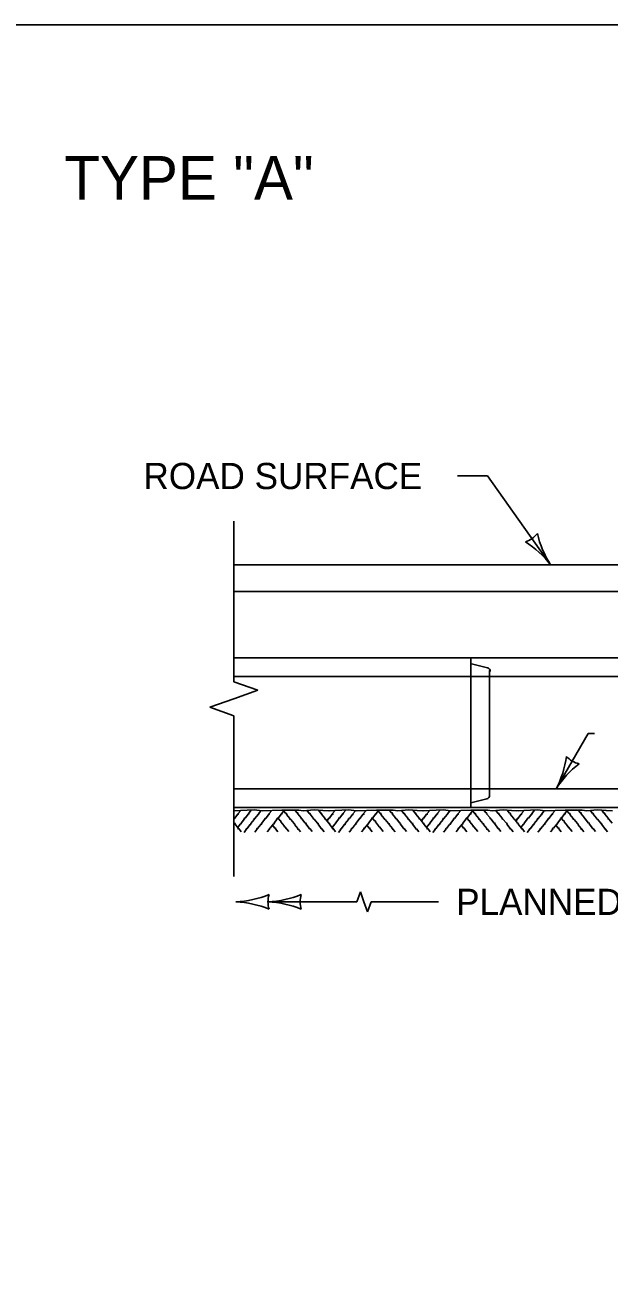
# Model space of a CAD drawing. Extents: x 49991.4 to 50022.1, y 49985 to 50011.4.
# Drawn here: x 50003.224 to 50004.56, y 49996.145 to 49998.999 of the extents above; entities that cross this region are included whole.
import ezdxf

# ---------------------------------------------------------------- set-up
doc = ezdxf.new("R2010")
doc.units = 0
for name, color, linetype in [('Level 1', 7, 'Continuous'), ('Level 2', 7, 'Continuous'), ('Level 3', 7, 'Continuous'), ('Level 4', 7, 'Continuous'), ('Level 6', 7, 'Continuous')]:
    doc.layers.add(name, color=color, linetype=linetype)

msp = doc.modelspace()

# ---------------------------------------------------------------- linework, layer by layer
at = {"layer": 'Level 1'}
for p, q in [((50003.7019, 49997.7029), (50003.702, 49997.7636)), ((50003.702, 49997.7636), (50004.9281, 49997.7636)), ((50005.2161, 49997.7029), (50003.7019, 49997.7029)), ((50003.7036, 49997.7029), (50003.7047, 49997.7029)), ((50003.702, 49997.5504), (50005.9421, 49997.5504)), ((50004.2441, 49997.5504), (50004.2441, 49997.208)), ((50006.3273, 49997.208), (50003.702, 49997.208))]:
    msp.add_line(p, q, dxfattribs=at)
msp.add_lwpolyline([(49999.3835, 49998.9992), (50016.7501, 49998.9992), (50016.7501, 49987.7988), (49999.3835, 49987.7988)], close=True, dxfattribs=at)
for points in [[(50003.7015, 49997.2006), (50003.7485, 49997.2025), (50003.7665, 49997.2004), (50003.8121, 49997.2019), (50003.8505, 49997.2022), (50003.8609, 49997.2007), (50003.8861, 49997.2025), (50003.9055, 49997.2013), (50003.9201, 49997.2006)], [(50003.7179, 49997.2012), (50003.7119, 49997.1941), (50003.7125, 49997.1926), (50003.7109, 49997.1926), (50003.7037, 49997.183), (50003.7029, 49997.183)], [(50003.742, 49997.202), (50003.736, 49997.195), (50003.7367, 49997.1936), (50003.7353, 49997.1936), (50003.7279, 49997.184), (50003.7258, 49997.184), (50003.7263, 49997.1824), (50003.7185, 49997.1726), (50003.7185, 49997.171), (50003.7168, 49997.1704), (50003.7108, 49997.1626)], [(50003.7639, 49997.2004), (50003.7585, 49997.1936), (50003.7589, 49997.1923), (50003.7577, 49997.1923), (50003.7503, 49997.1827), (50003.7483, 49997.1827), (50003.7485, 49997.181), (50003.7408, 49997.1713), (50003.7408, 49997.1696), (50003.7391, 49997.1689), (50003.7319, 49997.1596), (50003.7301, 49997.1593), (50003.7305, 49997.1576), (50003.7253, 49997.151)], [(50003.7888, 49997.2012), (50003.7828, 49997.1941), (50003.7835, 49997.1926), (50003.7821, 49997.1926), (50003.7749, 49997.183), (50003.7727, 49997.183), (50003.7729, 49997.1812), (50003.7654, 49997.1718), (50003.7654, 49997.1698), (50003.7635, 49997.1692), (50003.7564, 49997.1598), (50003.7545, 49997.1598), (50003.7549, 49997.1578), (50003.7497, 49997.1515)], [(50003.8173, 49997.202), (50003.8115, 49997.1947), (50003.8121, 49997.1935), (50003.8109, 49997.1935), (50003.8033, 49997.1839), (50003.8014, 49997.1839), (50003.8015, 49997.1822), (50003.7939, 49997.1726), (50003.7939, 49997.1707), (50003.7923, 49997.1702), (50003.7849, 49997.1608), (50003.7833, 49997.1606), (50003.7835, 49997.1587), (50003.7783, 49997.1524)], [(50003.8547, 49997.1524), (50003.8499, 49997.1587), (50003.8483, 49997.1584), (50003.8487, 49997.1598), (50003.841, 49997.169), (50003.8415, 49997.171), (50003.8397, 49997.1712), (50003.832, 49997.1808), (50003.8303, 49997.1812), (50003.8301, 49997.183), (50003.8225, 49997.1922), (50003.8229, 49997.1941), (50003.8211, 49997.1941), (50003.8158, 49997.2006)], [(50003.8811, 49997.153), (50003.8755, 49997.1602), (50003.874, 49997.1599), (50003.8743, 49997.1612), (50003.8667, 49997.1706), (50003.8673, 49997.1725), (50003.8653, 49997.1726), (50003.8577, 49997.1824), (50003.856, 49997.1827), (50003.8559, 49997.1845), (50003.8483, 49997.1936), (50003.8485, 49997.1956), (50003.8465, 49997.1956), (50003.8415, 49997.202)], [(50003.9089, 49997.1522), (50003.9034, 49997.1596), (50003.9019, 49997.1592), (50003.9021, 49997.1605), (50003.8949, 49997.1701), (50003.8951, 49997.1718), (50003.8933, 49997.172), (50003.8855, 49997.1816), (50003.8839, 49997.1821), (50003.8837, 49997.1838), (50003.8763, 49997.193), (50003.8764, 49997.1947), (50003.8745, 49997.1947), (50003.8695, 49997.2016)], [(50003.919, 49997.1726), (50003.9118, 49997.1816), (50003.9101, 49997.1822), (50003.91, 49997.1839), (50003.9023, 49997.193), (50003.9027, 49997.195), (50003.9009, 49997.195), (50003.8953, 49997.2019)], [(50003.9175, 49997.2006), (50003.9645, 49997.2025), (50003.9823, 49997.2004), (50004.0281, 49997.2019), (50004.0665, 49997.2022), (50004.0773, 49997.2007), (50004.1021, 49997.2025), (50004.1213, 49997.2013), (50004.1361, 49997.2006)], [(50003.9339, 49997.2012), (50003.9279, 49997.1941), (50003.9285, 49997.1926), (50003.9269, 49997.1926), (50003.9197, 49997.183), (50003.9189, 49997.183)], [(50003.958, 49997.202), (50003.952, 49997.195), (50003.9527, 49997.1936), (50003.9513, 49997.1936), (50003.9439, 49997.184), (50003.9418, 49997.184), (50003.9423, 49997.1824), (50003.9345, 49997.1726), (50003.9345, 49997.171), (50003.9328, 49997.1704), (50003.9267, 49997.1626)], [(50003.9799, 49997.2004), (50003.9743, 49997.1936), (50003.9749, 49997.1923), (50003.9735, 49997.1923), (50003.9663, 49997.1827), (50003.9643, 49997.1827), (50003.9645, 49997.181), (50003.9568, 49997.1713), (50003.9568, 49997.1696), (50003.9551, 49997.1689), (50003.9478, 49997.1596), (50003.9461, 49997.1593), (50003.9465, 49997.1576), (50003.9411, 49997.151)], [(50004.0048, 49997.2012), (50003.9987, 49997.1941), (50003.9994, 49997.1926), (50003.9981, 49997.1926), (50003.9905, 49997.183), (50003.9887, 49997.183), (50003.9889, 49997.1812), (50003.9813, 49997.1718), (50003.9813, 49997.1698), (50003.9795, 49997.1692), (50003.9723, 49997.1598), (50003.9705, 49997.1598), (50003.9709, 49997.1578), (50003.9657, 49997.1515)], [(50004.0333, 49997.202), (50004.0273, 49997.1947), (50004.0281, 49997.1935), (50004.0265, 49997.1935), (50004.0193, 49997.1839), (50004.0174, 49997.1839), (50004.0175, 49997.1822), (50004.0099, 49997.1726), (50004.0099, 49997.1707), (50004.0083, 49997.1702), (50004.0009, 49997.1608), (50003.9993, 49997.1606), (50003.9995, 49997.1587), (50003.9941, 49997.1524)], [(50004.0707, 49997.1524), (50004.0659, 49997.1587), (50004.0643, 49997.1584), (50004.0645, 49997.1598), (50004.057, 49997.169), (50004.0573, 49997.171), (50004.0557, 49997.1712), (50004.048, 49997.1808), (50004.0463, 49997.1812), (50004.0461, 49997.183), (50004.0385, 49997.1922), (50004.0389, 49997.1941), (50004.0369, 49997.1941), (50004.0318, 49997.2006)], [(50004.0971, 49997.153), (50004.0915, 49997.1602), (50004.09, 49997.1599), (50004.0901, 49997.1612), (50004.0827, 49997.1706), (50004.0829, 49997.1725), (50004.0813, 49997.1726), (50004.0737, 49997.1824), (50004.072, 49997.1827), (50004.0719, 49997.1845), (50004.0643, 49997.1936), (50004.0645, 49997.1956), (50004.0625, 49997.1956), (50004.0575, 49997.202)], [(50004.1249, 49997.1522), (50004.1194, 49997.1596), (50004.1179, 49997.1592), (50004.1181, 49997.1605), (50004.1105, 49997.1701), (50004.111, 49997.1718), (50004.1093, 49997.172), (50004.1015, 49997.1816), (50004.0999, 49997.1821), (50004.0997, 49997.1838), (50004.0923, 49997.193), (50004.0924, 49997.1947), (50004.0905, 49997.1947), (50004.0855, 49997.2016)], [(50004.135, 49997.1726), (50004.1278, 49997.1816), (50004.126, 49997.1822), (50004.1259, 49997.1839), (50004.1183, 49997.193), (50004.1185, 49997.195), (50004.1165, 49997.195), (50004.1113, 49997.2019)], [(50004.1335, 49997.2006), (50004.1805, 49997.2025), (50004.1983, 49997.2004), (50004.2441, 49997.2019), (50004.2825, 49997.2022), (50004.2929, 49997.2007), (50004.318, 49997.2025), (50004.3373, 49997.2013), (50004.3521, 49997.2006)], [(50004.1499, 49997.2012), (50004.1439, 49997.1941), (50004.1445, 49997.1926), (50004.1429, 49997.1926), (50004.1357, 49997.183), (50004.1349, 49997.183)], [(50004.1739, 49997.202), (50004.168, 49997.195), (50004.1685, 49997.1936), (50004.1673, 49997.1936), (50004.1597, 49997.184), (50004.1578, 49997.184), (50004.1579, 49997.1824), (50004.1503, 49997.1726), (50004.1503, 49997.171), (50004.1487, 49997.1704), (50004.1427, 49997.1626)], [(50004.1959, 49997.2004), (50004.1905, 49997.1936), (50004.1909, 49997.1923), (50004.1897, 49997.1923), (50004.1823, 49997.1827), (50004.1803, 49997.1827), (50004.1805, 49997.181), (50004.1728, 49997.1713), (50004.1728, 49997.1696), (50004.1711, 49997.1689), (50004.1638, 49997.1596), (50004.162, 49997.1593), (50004.1623, 49997.1576), (50004.1571, 49997.151)], [(50004.2208, 49997.2012), (50004.2147, 49997.1941), (50004.2154, 49997.1926), (50004.2141, 49997.1926), (50004.2065, 49997.183), (50004.2047, 49997.183), (50004.2049, 49997.1812), (50004.1973, 49997.1718), (50004.1973, 49997.1698), (50004.1955, 49997.1692), (50004.1883, 49997.1598), (50004.1865, 49997.1598), (50004.1867, 49997.1578), (50004.1815, 49997.1515)], [(50004.2493, 49997.202), (50004.2433, 49997.1947), (50004.2441, 49997.1935), (50004.2425, 49997.1935), (50004.2353, 49997.1839), (50004.2334, 49997.1839), (50004.2335, 49997.1822), (50004.2259, 49997.1726), (50004.2259, 49997.1707), (50004.2243, 49997.1702), (50004.2169, 49997.1608), (50004.2149, 49997.1606), (50004.2154, 49997.1587), (50004.2101, 49997.1524)], [(50004.2867, 49997.1524), (50004.2819, 49997.1587), (50004.2803, 49997.1584), (50004.2805, 49997.1598), (50004.273, 49997.169), (50004.2733, 49997.171), (50004.2717, 49997.1712), (50004.264, 49997.1808), (50004.2623, 49997.1812), (50004.2621, 49997.183), (50004.2544, 49997.1922), (50004.2549, 49997.1941), (50004.2529, 49997.1941), (50004.2478, 49997.2006)], [(50004.3129, 49997.153), (50004.3075, 49997.1602), (50004.306, 49997.1599), (50004.3061, 49997.1612), (50004.2987, 49997.1706), (50004.2989, 49997.1725), (50004.2973, 49997.1726), (50004.2897, 49997.1824), (50004.288, 49997.1827), (50004.2879, 49997.1845), (50004.2801, 49997.1936), (50004.2805, 49997.1956), (50004.2785, 49997.1956), (50004.2735, 49997.202)], [(50004.3408, 49997.1522), (50004.3354, 49997.1596), (50004.3337, 49997.1592), (50004.3341, 49997.1605), (50004.3265, 49997.1701), (50004.327, 49997.1718), (50004.3253, 49997.172), (50004.3175, 49997.1816), (50004.3159, 49997.1821), (50004.3157, 49997.1838), (50004.3079, 49997.193), (50004.3084, 49997.1947), (50004.3065, 49997.1947), (50004.3015, 49997.2016)], [(50004.3509, 49997.1726), (50004.3437, 49997.1816), (50004.342, 49997.1822), (50004.3419, 49997.1839), (50004.3343, 49997.193), (50004.3345, 49997.195), (50004.3325, 49997.195), (50004.3273, 49997.2019)], [(50004.3495, 49997.2006), (50004.3965, 49997.2025), (50004.4143, 49997.2004), (50004.4599, 49997.2019), (50004.4983, 49997.2022), (50004.5089, 49997.2007), (50004.534, 49997.2025), (50004.5533, 49997.2013), (50004.5679, 49997.2006)], [(50004.3659, 49997.2012), (50004.3599, 49997.1941), (50004.3605, 49997.1926), (50004.3589, 49997.1926), (50004.3515, 49997.183), (50004.3505, 49997.183)], [(50004.3899, 49997.202), (50004.3839, 49997.195), (50004.3845, 49997.1936), (50004.3833, 49997.1936), (50004.3757, 49997.184), (50004.3738, 49997.184), (50004.3739, 49997.1824), (50004.3663, 49997.1726), (50004.3663, 49997.171), (50004.3647, 49997.1704), (50004.3587, 49997.1626)], [(50004.4119, 49997.2004), (50004.4063, 49997.1936), (50004.4069, 49997.1923), (50004.4055, 49997.1923), (50004.3983, 49997.1827), (50004.3963, 49997.1827), (50004.3965, 49997.181), (50004.3888, 49997.1713), (50004.3888, 49997.1696), (50004.3871, 49997.1689), (50004.3798, 49997.1596), (50004.378, 49997.1593), (50004.3783, 49997.1576), (50004.3731, 49997.151)], [(50004.4367, 49997.2012), (50004.4307, 49997.1941), (50004.4314, 49997.1926), (50004.4299, 49997.1926), (50004.4225, 49997.183), (50004.4207, 49997.183), (50004.4209, 49997.1812), (50004.4133, 49997.1718), (50004.4133, 49997.1698), (50004.4115, 49997.1692), (50004.4043, 49997.1598), (50004.4023, 49997.1598), (50004.4027, 49997.1578), (50004.3975, 49997.1515)], [(50004.4651, 49997.202), (50004.4593, 49997.1947), (50004.4601, 49997.1935), (50004.4585, 49997.1935), (50004.4513, 49997.1839), (50004.4493, 49997.1839), (50004.4495, 49997.1822), (50004.4419, 49997.1726), (50004.4419, 49997.1707), (50004.4403, 49997.1702), (50004.4329, 49997.1608), (50004.4309, 49997.1606), (50004.4314, 49997.1587), (50004.4261, 49997.1524)], [(50004.5027, 49997.1524), (50004.4979, 49997.1587), (50004.4961, 49997.1584), (50004.4965, 49997.1598), (50004.489, 49997.169), (50004.4893, 49997.171), (50004.4877, 49997.1712), (50004.48, 49997.1808), (50004.4783, 49997.1812), (50004.4781, 49997.183), (50004.4704, 49997.1922), (50004.4709, 49997.1941), (50004.4689, 49997.1941), (50004.4638, 49997.2006)], [(50004.5291, 49997.153), (50004.5235, 49997.1602), (50004.5219, 49997.1599), (50004.5221, 49997.1612), (50004.5147, 49997.1706), (50004.5149, 49997.1725), (50004.5133, 49997.1726), (50004.5057, 49997.1824), (50004.504, 49997.1827), (50004.5039, 49997.1845), (50004.4961, 49997.1936), (50004.4965, 49997.1956), (50004.4945, 49997.1956), (50004.4895, 49997.202)], [(50004.5568, 49997.1522), (50004.5514, 49997.1596), (50004.5497, 49997.1592), (50004.5501, 49997.1605), (50004.5425, 49997.1701), (50004.543, 49997.1718), (50004.5411, 49997.172), (50004.5335, 49997.1816), (50004.5319, 49997.1821), (50004.5315, 49997.1838), (50004.5239, 49997.193), (50004.5244, 49997.1947), (50004.5225, 49997.1947), (50004.5175, 49997.2016)], [(50004.5669, 49997.1726), (50004.5597, 49997.1816), (50004.558, 49997.1822), (50004.5579, 49997.1839), (50004.5503, 49997.193), (50004.5505, 49997.195), (50004.5485, 49997.195), (50004.5433, 49997.2019)], [(50003.7189, 49997.1524), (50003.7133, 49997.1598), (50003.7119, 49997.1593), (50003.7121, 49997.1606), (50003.7047, 49997.1701), (50003.7049, 49997.1719), (50003.7031, 49997.172), (50003.7029, 49997.1726)], [(50003.8027, 49997.1527), (50003.7973, 49997.1593), (50003.7975, 49997.1612), (50003.7955, 49997.1612), (50003.7905, 49997.168)], [(50003.8277, 49997.1532), (50003.8189, 49997.1642), (50003.8173, 49997.1646), (50003.8171, 49997.1662), (50003.8097, 49997.1755), (50003.8098, 49997.1773), (50003.808, 49997.1773), (50003.8031, 49997.1839)], [(50003.9189, 49997.183), (50003.9178, 49997.183), (50003.9179, 49997.1812), (50003.9153, 49997.1778)], [(50003.9347, 49997.1524), (50003.9293, 49997.1598), (50003.9279, 49997.1593), (50003.928, 49997.1606), (50003.9207, 49997.1701), (50003.9209, 49997.1719), (50003.9191, 49997.172), (50003.9185, 49997.1726)], [(50004.0185, 49997.1527), (50004.0133, 49997.1593), (50004.0135, 49997.1612), (50004.0115, 49997.1612), (50004.0065, 49997.168)], [(50004.0437, 49997.1532), (50004.0349, 49997.1642), (50004.0333, 49997.1646), (50004.0331, 49997.1662), (50004.0257, 49997.1755), (50004.0258, 49997.1773), (50004.024, 49997.1773), (50004.0191, 49997.1839)], [(50004.1349, 49997.183), (50004.1338, 49997.183), (50004.1339, 49997.1812), (50004.1313, 49997.1778)], [(50004.1507, 49997.1524), (50004.1453, 49997.1598), (50004.1439, 49997.1593), (50004.1441, 49997.1606), (50004.1365, 49997.1701), (50004.1369, 49997.1719), (50004.1351, 49997.172), (50004.1349, 49997.1726)], [(50004.2345, 49997.1527), (50004.2293, 49997.1593), (50004.2295, 49997.1612), (50004.2275, 49997.1612), (50004.2225, 49997.168)], [(50004.2597, 49997.1532), (50004.2509, 49997.1642), (50004.2493, 49997.1646), (50004.2491, 49997.1662), (50004.2417, 49997.1755), (50004.2418, 49997.1773), (50004.24, 49997.1773), (50004.2349, 49997.1839)], [(50004.3509, 49997.183), (50004.3498, 49997.183), (50004.3499, 49997.1812), (50004.3473, 49997.1778)], [(50004.3667, 49997.1524), (50004.3613, 49997.1598), (50004.3599, 49997.1593), (50004.36, 49997.1606), (50004.3525, 49997.1701), (50004.3528, 49997.1719), (50004.3511, 49997.172), (50004.3505, 49997.1726)], [(50004.4505, 49997.1527), (50004.4451, 49997.1593), (50004.4455, 49997.1612), (50004.4435, 49997.1612), (50004.4383, 49997.168)], [(50004.4757, 49997.1532), (50004.4669, 49997.1642), (50004.4653, 49997.1646), (50004.4651, 49997.1662), (50004.4575, 49997.1755), (50004.4578, 49997.1773), (50004.456, 49997.1773), (50004.4509, 49997.1839)]]:
    msp.add_lwpolyline(points, dxfattribs=at)
at = {"layer": 'Level 3'}
for p, q in [((50004.2137, 49997.9669), (50004.2822, 49997.9669)), ((50004.2822, 49997.9669), (50004.4264, 49997.7636)), ((50004.5124, 49997.3777), (50004.4392, 49997.2508)), ((50004.5124, 49997.3777), (50004.5267, 49997.3777)), ((50003.9834, 49996.9922), (50003.78, 49996.9922)), ((50003.9915, 49997.015), (50003.9834, 49996.9922)), ((50003.9915, 49997.015), (50003.9996, 49996.9922)), ((50003.9996, 49996.9922), (50004.0077, 49996.9694)), ((50004.0158, 49996.9922), (50004.0077, 49996.9694)), ((50004.1704, 49996.9922), (50004.0158, 49996.9922))]:
    msp.add_line(p, q, dxfattribs=at)
for centre, radius, start, end in [((50004.3522, 49997.8682), 0.0548, 287.4837, 323.2061), ((50004.6129, 49997.8846), 0.2223, 192.8009, 212.9844), ((50004.2432, 49997.6196), 0.233, 38.1722, 57.422), ((50004.2319, 49997.3571), 0.233, 332.8577, 352.1076), ((50004.6271, 49997.1319), 0.2223, 127.4864, 147.67), ((50004.5032, 49997.3619), 0.0548, 222.1693, 257.8916), ((50003.6951, 49997.2249), 0.233, 272.8273, 292.0772), ((50003.6974, 49996.7701), 0.2223, 67.456, 87.6395), ((50003.8348, 49996.9922), 0.0548, 162.1388, 197.8612), ((50003.7685, 49997.2249), 0.233, 272.8273, 292.0772), ((50003.7709, 49996.7701), 0.2223, 67.456, 87.6395), ((50003.9083, 49996.9922), 0.0548, 162.1388, 197.8612)]:
    msp.add_arc(centre, radius, start, end, dxfattribs=at)
at = {"layer": 'Level 4'}
for p, q in [((50004.2456, 49997.5373), (50004.282, 49997.5281)), ((50003.702, 49997.5077), (50005.9483, 49997.5077)), ((50004.287, 49997.5221), (50004.287, 49997.2363)), ((50003.702, 49997.2508), (50006.3273, 49997.2508)), ((50004.2441, 49997.2188), (50004.2805, 49997.2279))]:
    msp.add_line(p, q, dxfattribs=at)
for centre, start, end in [((50004.2799, 49997.5198), 0, 75.8703), ((50004.2784, 49997.2362), 284.1107, 0)]:
    msp.add_arc(centre, 0.00856, start, end, dxfattribs=at)
at = {"layer": 'Level 6'}
for p, q in [((50003.702, 49997.8636), (50003.702, 49997.4959)), ((50003.7568, 49997.4764), (50003.702, 49997.4959)), ((50003.7568, 49997.4764), (50003.702, 49997.457)), ((50003.702, 49997.457), (50003.6472, 49997.4376)), ((50003.702, 49997.4181), (50003.6472, 49997.4376)), ((50003.702, 49997.4181), (50003.702, 49997.0505))]:
    msp.add_line(p, q, dxfattribs=at)

# ---------------------------------------------------------------- texts
at = {"layer": 'Level 2'}
for s, height, p in [('TYPE "A"', 0.1, (50003.3142, 49998.5992)), ('ROAD SURFACE', 0.06, (50003.4954, 49997.9369)), ('PLANNED CULVERT LENGTH', 0.06, (50004.2104, 49996.9622))]:
    msp.add_text(s, height=height, dxfattribs=at).set_placement(p)

doc.saveas('drawing.dxf')
